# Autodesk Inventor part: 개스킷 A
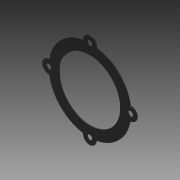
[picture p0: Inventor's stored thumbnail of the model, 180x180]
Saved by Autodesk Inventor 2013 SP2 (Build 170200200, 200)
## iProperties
Created: 2020-03
Part Number: 개스킷 A
Material: 고무
Document SubType Name: Modeling
Designer: mduedu
Density: 0.93 g/cm^3
Mass: 2.68337 g
Surface Area: 63.575 cm^2
Volume: 2.88534 cm^3
Author: mduedu
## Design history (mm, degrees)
sketch "스케치1" dims "d1" = 88
  geometry: C1 r 33 at (0, 0); C2 r 7 at (0, 44); C3 r 7 at (-38.105, -22); C4 r 7 at (38.105, -22); 2 further points
  constraints: 4 centre point, 2 coincident, 2 vertical alignment, 9 other
  dimensions: "d0" = 66 diameter of C1; "d2" = 14 diameter of C2; "d5" = 360 deg dimension on point (0, 0) C2.centre (derived)
extrude "돌출1" new body sketch "스케치1" distance "d7" = 1; taper "d8" = 0 deg
extrude "돌출2" join sketch "스케치1" stored distance "d17" = 10; taper "d18" = 0 deg
fillet "모깎기1" dims "d9" = 1
sketch "스케치2"
  geometry: C1 r 33 at (0, 0) reference; A1 r 44 centre (0, 0) between (-7.817, 43.3) and (7.817, 43.3) reference; A2 r 7 centre (0, 44) between (6.996, 44.249) and (-6.996, 44.249) reference; A3 r 1 centre (7.995, 44.284) between (6.996, 44.249) and (7.817, 43.3) reference; A4 r 1 centre (-7.995, 44.284) between (-7.817, 43.3) and (-6.996, 44.249) reference; 4 further points
hole "구멍1" sketch "스케치2" diameter "d10" = 5.5; stored, may be unused: countersink angle "d14" = 90 deg, drill point angle "d16" = 118 deg; dims "d11" = 6, "d12" = 10, "d13" = 5.7, "d15" = 8
node "솔리드1"
pattern_circular "원형 패턴1" dims "d20" = 360 deg
node "투영된 루프1"
